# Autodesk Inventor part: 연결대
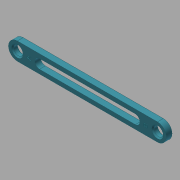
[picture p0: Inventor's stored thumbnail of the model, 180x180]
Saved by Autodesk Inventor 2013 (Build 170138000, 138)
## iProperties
Created: 2017-07
Part Number: 연결대
Material: 스테인리스강
Document SubType Name: Modeling
Designer: mduedu
Density: 1 g/cm^3
Author: mduedu
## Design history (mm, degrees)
sketch "스케치1"
  geometry: L1 (-67.5, 0)-(67.5, 0); L2 (-67.5, -7.5)-(67.5, -7.5); L3 (67.5, -7.5)-(67.5, 7.5); L4 (67.5, 7.5)-(-67.5, 7.5); L5 (-67.5, 7.5)-(-67.5, -7.5); L6 (-67.5, -7.5)-(67.5, 7.5); L7 (67.5, -7.5)-(-67.5, 7.5); 2 further points
  constraints: 14 end point, 4 midpoint, 2 horizontal, 2 parallel, 1 coincident, 1 perpendicular
  dimensions: "d0" = 135 distance of L1.start L1.end; "d2" = 15 distance of L2.end L3.end
extrude "돌출1" new body sketch "스케치1" distance "d3" = 5; taper "d4" = 0 deg
fillet "모깎기1"
fillet "모깎기2"
sketch "스케치2"
  geometry: C1 r 4 at (60, 0); A1 r 7.5 centre (60, 0) between (60, -7.5) and (60, 7.5) reference; 1 further point
  constraints: 1 centre point, 1 coincident
  dimensions: "d5" = 8 diameter of C1
extrude "돌출2" cut sketch "스케치2" stored distance "d6" = 10; taper "d7" = 0 deg
chamfer "모따기1" distance "d8" = 1; stored, may be unused: second distance "d9" = 2, angle "d10" = 45 deg
sketch "스케치3"
  geometry: L1 (-45, 0)-(45, 0); L2 (-45, -4)-(45, -4); L3 (45, -4)-(45, 4); L4 (45, 4)-(-45, 4); L5 (-45, 4)-(-45, -4); L6 (-45, -4)-(45, 4); L7 (45, -4)-(-45, 4); 2 further points
  constraints: 14 end point, 4 midpoint, 2 horizontal, 2 parallel, 1 coincident, 1 perpendicular
  dimensions: "d11" = 90 distance of L1.start L1.end; "d13" = 8 distance of L2.end L3.end
extrude "돌출3" cut sketch "스케치3" stored distance "d14" = 10; taper "d15" = 0 deg
fillet "모깎기3"
fillet "모깎기4"
sketch "스케치4"
  geometry: L1 (-60, 0)-(60, 0); C1 r 5 at (-60, 0) reference; C2 r 5 at (60, 0) reference; 3 further points
  constraints: 2 end point, 2 point on line, 1 horizontal, 2 other
  dimensions: "d16" = 50 distance of point (-50, 0) point (0, 0); "d17" = 50 distance of point (50, 0) point (0, 0)
feature "엠보싱1" sketch "스케치4" dims "d0" = 135, "d2" = 15, "d18" = 0.5, "d19" = 0
node "솔리드1"
mirror "대칭1"
